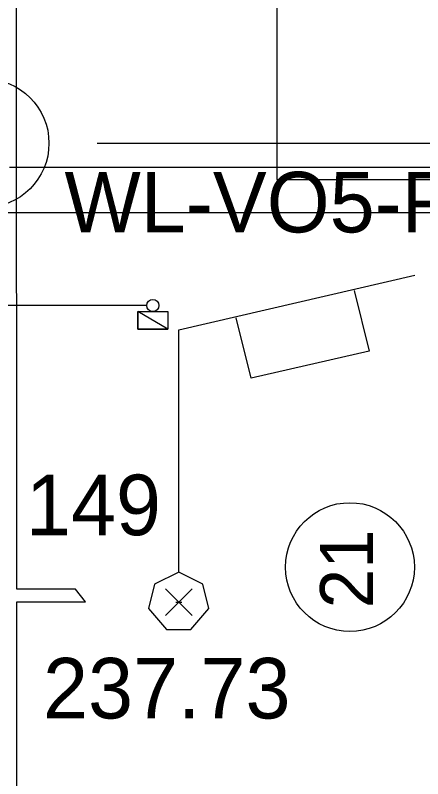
# Model space of a CAD drawing. Extents: x -264222 to -263592, y -1242345 to -1242048.
# Drawn here: x -263918.62 to -263911.88, y -1242220.38 to -1242207.77 of the extents above; entities that cross this region are included whole.
import ezdxf

# ---------------------------------------------------------------- set-up
doc = ezdxf.new("R2010")
doc.units = 0
for name, color, linetype in [('BOD_CISLO', 7, 'Continuous'), ('BOD_SYMBOL', 7, 'Continuous'), ('BOD_VYSKA', 7, 'Continuous'), ('HESCON_OSI_STAVBY_KFA', 7, 'Continuous'), ('KFA_2D_SITUACIA_DSP', 7, 'Continuous'), ('KFA_SO_62-1_VO_LAMPY_MERANE', 7, 'Continuous'), ('KFA_SO_62-1_VO_POPIS_LAMP_PROJEKT', 7, 'Continuous'), ('KFA_SO_62-1_VO_TRASA_KABLOV_PROJEKT', 7, 'Continuous')]:
    doc.layers.add(name, color=color, linetype=linetype)

msp = doc.modelspace()

# ---------------------------------------------------------------- linework, layer by layer
at = {"layer": 'BOD_SYMBOL'}
for p, q in [((-263916.136, -1242217.684), (-263915.694, -1242217.242)), ((-263915.694, -1242217.684), (-263916.136, -1242217.242))]:
    msp.add_line(p, q, dxfattribs=at)
at = {"layer": 'HESCON_OSI_STAVBY_KFA'}
msp.add_line((-263917.265, -1242209.882), (-263905.505, -1242209.882), dxfattribs=at)
msp.add_line((-263917.265, -1242209.882), (-263905.505, -1242209.882), dxfattribs=at)
for centre in [(-263919.123, -1242209.882), (-263913.085, -1242216.882)]:
    msp.add_circle(centre, 1.064, dxfattribs=at)
at = {"layer": 'KFA_2D_SITUACIA_DSP'}
for p, q in [((-263908.718, -1242210.282), (-263918.714, -1242210.282)), ((-263903.343, -1242211.032), (-263921.351, -1242211.032)), ((-263916.443, -1242212.562), (-263925.798, -1242212.562)), ((-263916.593, -1242212.952), (-263916.593, -1242212.662)), ((-263916.593, -1242212.662), (-263916.093, -1242212.662)), ((-263916.093, -1242212.952), (-263916.593, -1242212.662)), ((-263916.093, -1242212.952), (-263916.593, -1242212.662)), ((-263916.593, -1242212.662), (-263916.593, -1242212.952)), ((-263916.093, -1242212.662), (-263916.093, -1242212.952)), ((-263916.093, -1242212.952), (-263916.593, -1242212.952)), ((-263916.593, -1242212.952), (-263916.093, -1242212.952))]:
    msp.add_line(p, q, dxfattribs=at)
msp.add_lwpolyline([(-263893.618, -1242118.282), (-263916.093, -1242118.282), (-263916.093, -1242175.482), (-263914.293, -1242175.482), (-263914.293, -1242210.482), (-263893.618, -1242210.482), (-263893.618, -1242166.382), (-263900.043, -1242166.382), (-263900.043, -1242162.382), (-263893.618, -1242162.382)], close=True, dxfattribs=at)
msp.add_circle((-263916.343, -1242212.562), 0.1, dxfattribs=at)
at = {"layer": 'KFA_SO_62-1_VO_LAMPY_MERANE'}
for p, q in [((-263915.965, -1242217.463), (-263915.865, -1242217.463)), ((-263915.915, -1242217.463), (-263915.915, -1242217.463))]:
    msp.add_line(p, q, dxfattribs=at)
for points in [[(-263915.915, -1242216.963), (-263916.315, -1242217.163), (-263916.415, -1242217.563), (-263916.115, -1242217.913), (-263915.715, -1242217.913), (-263915.415, -1242217.563), (-263915.515, -1242217.163), (-263915.915, -1242216.963), (-263915.915, -1242212.963), (-263912.015, -1242212.063)], [(-263913.015, -1242212.313), (-263912.765, -1242213.313), (-263914.715, -1242213.763), (-263914.965, -1242212.763)]]:
    msp.add_lwpolyline(points, dxfattribs=at)
at = {"layer": 'KFA_SO_62-1_VO_TRASA_KABLOV_PROJEKT'}
for p, q in [((-263918.593, -1242217.248), (-263918.595, -1242195.35)), ((-263917.621, -1242217.248), (-263918.593, -1242217.248)), ((-263917.457, -1242217.457), (-263917.621, -1242217.248)), ((-263918.592, -1242237.807), (-263918.592, -1242217.457)), ((-263918.592, -1242217.457), (-263917.457, -1242217.457))]:
    msp.add_line(p, q, dxfattribs=at)

# ---------------------------------------------------------------- texts
at = {"layer": 'BOD_CISLO'}
msp.add_text('149', height=1, dxfattribs=at).set_placement((-263918.439, -1242216.355))
at = {"layer": 'BOD_VYSKA'}
msp.add_text('237.73', height=1, dxfattribs=at).set_placement((-263918.157, -1242219.382))
at = {"layer": 'HESCON_OSI_STAVBY_KFA'}
msp.add_text('21', height=0.875, rotation=90, dxfattribs=at).set_placement((-263912.704, -1242217.562))
at = {"layer": 'KFA_SO_62-1_VO_POPIS_LAMP_PROJEKT'}
msp.add_text('WL-VO5-RH2', height=1, dxfattribs=at).set_placement((-263917.803, -1242211.354))

doc.saveas('drawing.dxf')
